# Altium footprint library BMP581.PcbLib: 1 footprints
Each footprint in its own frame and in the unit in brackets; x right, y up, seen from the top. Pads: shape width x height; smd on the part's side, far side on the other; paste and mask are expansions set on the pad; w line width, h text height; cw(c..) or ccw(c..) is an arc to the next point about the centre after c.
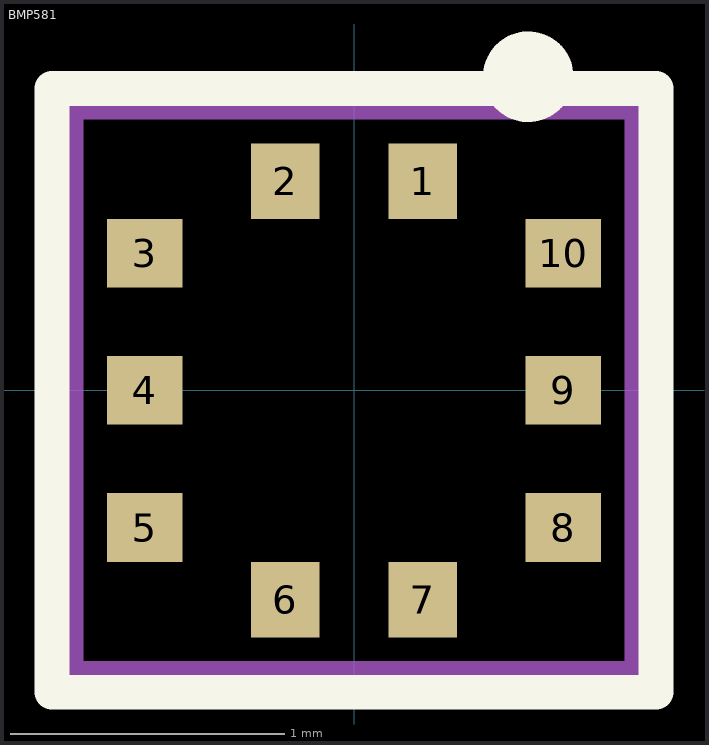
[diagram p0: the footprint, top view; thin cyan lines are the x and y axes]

## BMP581 [mm]
pads (10):
  rect 0.25x0.275 smd paste-1: 1(0.25,0.763) 2(-0.25,0.763) 6(-0.25,-0.763) 7(0.25,-0.763)
  rect 0.275x0.25 smd paste-0.025: 3(-0.763,0.5) 4(-0.763,0) 5(-0.763,-0.5) 8(0.763,-0.5) 9(0.763,0) 10(0.763,0.5)
Top Overlay:
  circle w0.178: c0.635,1.143 r0.076
  lines w0.127: -1.1,-1.1 1.1,-1.1 1.1,1.1 -1.1,1.1 -1.1,-1.1
Top Paste:
  region: -0.15,0.65 -0.35,0.65 -0.35,0.875 -0.15,0.875
  region: -0.15,-0.875 -0.35,-0.875 -0.35,-0.65 -0.15,-0.65
  region: 0.35,0.65 0.15,0.65 0.15,0.875 0.35,0.875
  region: 0.35,-0.875 0.15,-0.875 0.15,-0.65 0.35,-0.65
Assembly Top:
  lines w0.127: -1.05,-1.05 1.05,-1.05 1.05,1.05 -1.05,1.05 -1.05,-1.05
3D body "step_temp.STEP": height 0.8, standoff 0, extent -1,-1 1,1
